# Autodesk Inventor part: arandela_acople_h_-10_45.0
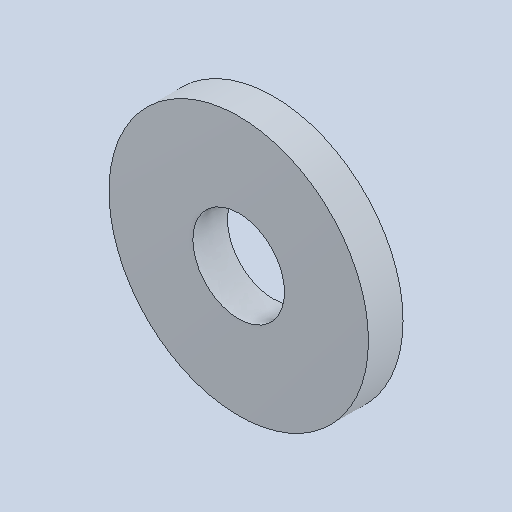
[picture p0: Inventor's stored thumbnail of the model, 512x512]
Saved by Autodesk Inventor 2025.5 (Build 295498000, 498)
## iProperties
Created: 2026-10
Part Number: arandela_acople_h_-10_45.0
Material: Genérico
Document SubType Name: Modeling
Designer: Luis M
Density: 1 g/cm^3
Appearance: Valor por defecto
Author: Luis M
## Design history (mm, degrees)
feature "Base1"
node "Sólido1"
